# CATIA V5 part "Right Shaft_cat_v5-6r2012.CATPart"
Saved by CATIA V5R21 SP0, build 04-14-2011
Part number: Right hand shaft
Bounding box of the stored display mesh (mm): x 0 to 100, y -35 to 35, z -35 to 35
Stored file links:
  D:\CATIA V5R21 E-RESOURCES\CATIA-V5R21\catia-v5r21-Tut\c16-catia-v5r21-tut\c16-catia-v5r21-tut02\Right Shaft_cat_v5r21.CATPart
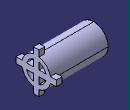
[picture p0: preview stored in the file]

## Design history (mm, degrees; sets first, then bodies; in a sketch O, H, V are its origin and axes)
Body1 (main body)
  Sketch1 on yz-plane, origin (0, 0, 0), H (0, 1, 0), V (0, 0, 1)
    circle A1 centre (0, 0) radius 25
    circle A2 centre (0, 0) radius 17.5
    radius A1 = 25
    radius A2 = 17.5
  Pad1: profile Sketch1, direction (1, 0, 0), length 100
  Sketch2 on end face of Pad1, origin (100, 0, 0), H (0, 1, 0), V (0, 0, 1)
    line L1 (5, 35) -> (5, -35)
    line L2 (5, -35) -> (-5, -35)
    line L3 (-5, -35) -> (-5, 35)
    line L4 (-5, 35) -> (5, 35)
    length L1 = 70
    length L4 = 10
    vertical: L1 V, L3 V
    horizontal: L2 H, L4 H
    equidistance: L1 L3 O, L2 L4 O
  Pad2: profile Sketch2, direction (-1, 0, 0), length 10
  CircPattern1: of the body so far, instances 2, angular step 90, axis from face of Pad1 from Sketch1.A1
